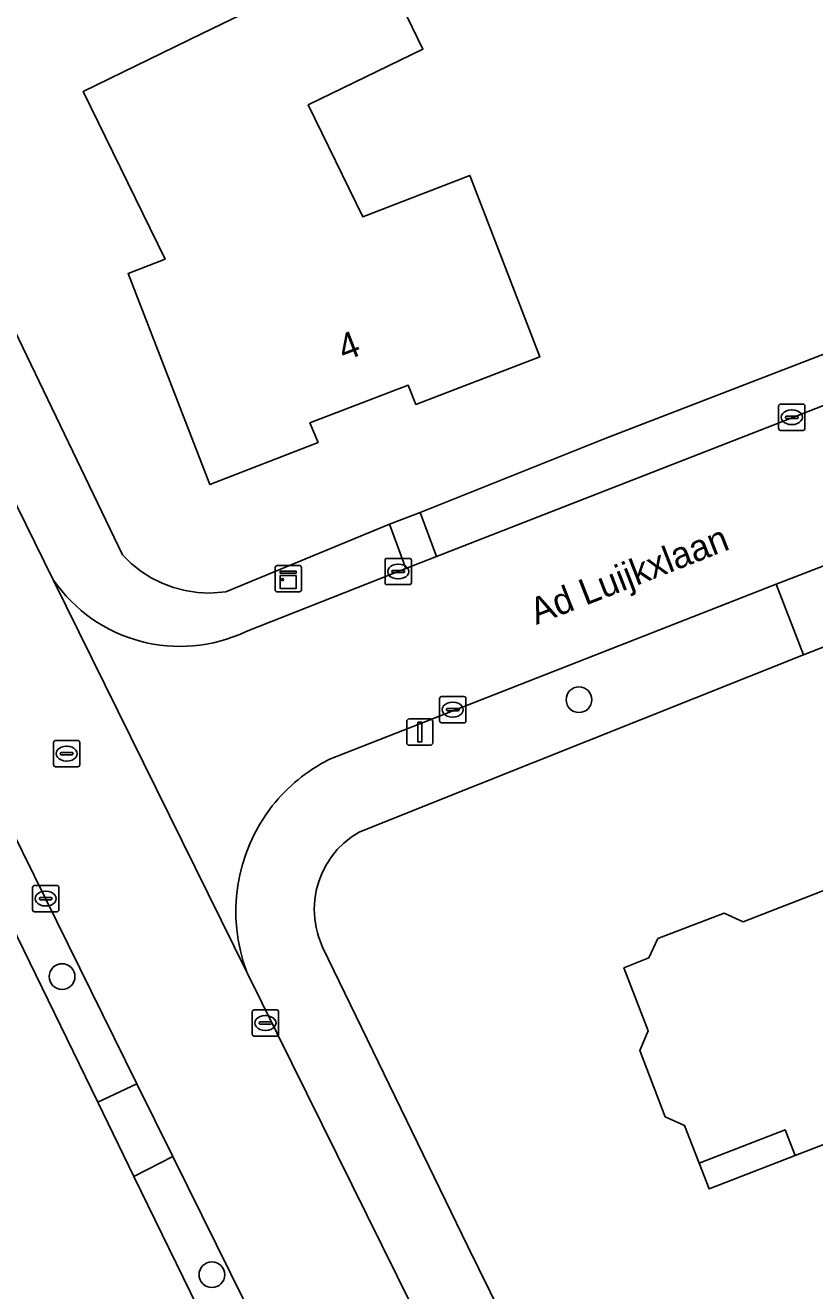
# Model space of a CAD drawing. Extents: x 157320 to 158835, y 386650 to 388491.
# Drawn here: x 158149.26 to 158179.28, y 386981.58 to 387029.67 of the extents above; entities that cross this region are included whole.
import ezdxf

# ---------------------------------------------------------------- set-up
doc = ezdxf.new("R2010")
doc.units = 0
for name, color, linetype in [('IMGEO_Boom', 7, 'Continuous'), ('IMGEO_Erf', 7, 'Continuous'), ('IMGEO_Groenvoorziening', 7, 'Continuous'), ('IMGEO_Hek', 7, 'Continuous'), ('IMGEO_Kast', 7, 'Continuous'), ('IMGEO_Kolk', 7, 'Continuous'), ('IMGEO_Lichtmast', 7, 'Continuous'), ('IMGEO_Openbare_ruimte_label', 7, 'Continuous'), ('IMGEO_Pand', 7, 'Continuous'), ('IMGEO_Pand_nummerreeks', 7, 'Continuous'), ('IMGEO_Pand_overbouw', 7, 'Continuous'), ('IMGEO_Rijbaan_lokaal_gesloten', 7, 'Continuous'), ('IMGEO_Rijbaan_lokaal_open', 7, 'Continuous'), ('IMGEO_Rioolput', 7, 'Continuous'), ('IMGEO_Voetpad_open', 7, 'Continuous')]:
    doc.layers.add(name, color=color, linetype=linetype)

msp = doc.modelspace()

# ---------------------------------------------------------------- linework, layer by layer
at = {"layer": 'IMGEO_Boom'}
for centre in [(158170.316, 387004.038), (158150.658, 386993.515), (158156.355, 386982.186)]:
    msp.add_circle(centre, 0.489, dxfattribs=at)
at = {"layer": 'IMGEO_Erf'}
for points in [[(158157.696, 386977.099), (158153.389, 386985.92), (158152.012, 386988.74), (158146.345, 387000.348), (158144.612, 387003.884), (158143.428, 387006.237), (158136.533, 387019.939), (158134.023, 387024.867), (158126.593, 387040.135), (158124.413, 387044.539), (158121.773, 387050.005), (158120.091, 387053.487), (158116.048, 387061.855)], [(158139.379, 387037.621), (158145.728, 387024.479), (158148.376, 387019.052), (158152.961, 387009.538), (158153.291, 387009.212), (158153.654, 387008.922), (158154.045, 387008.672), (158154.46, 387008.464), (158154.895, 387008.301), (158155.344, 387008.184), (158155.803, 387008.115), (158156.266, 387008.093), (158156.73, 387008.121), (158156.891, 387008.142), (158163.114, 387010.708), (158164.275, 387011.156), (158171.314, 387013.97), (158200.402, 387025.18)], [(158184.426, 387007.92), (158178.863, 387005.743), (158164.455, 387000), (158161.952, 386999.002), (158161.654, 386998.81), (158161.378, 386998.589), (158161.127, 386998.34), (158160.903, 386998.065), (158160.709, 386997.769), (158160.547, 386997.455), (158160.419, 386997.125), (158160.326, 386996.783), (158160.269, 386996.434), (158160.249, 386996.08), (158160.266, 386995.727), (158160.32, 386995.377), (158160.372, 386995.178), (158160.41, 386995.035), (158160.564, 386994.64), (158166.088, 386983.262), (158171.163, 386972.978), (158172.603, 386970.061), (158172.633, 386970.001), (158181.572, 386970.234)]]:
    msp.add_lwpolyline(points, dxfattribs=at)
for points in [[(158162.548, 387032.541), (158164.384, 387028.764), (158160.022, 387026.644), (158162.091, 387022.388), (158166.167, 387023.964), (158167.029, 387021.736), (158168.833, 387017.072), (158164.111, 387015.261), (158163.822, 387015.989), (158160.085, 387014.554), (158160.396, 387013.816), (158156.273, 387012.213), (158153.168, 387020.235), (158154.576, 387020.78), (158151.462, 387027.153), (158155.959, 387029.339), (158158.186, 387030.421)], [(158178.542, 386986.711), (158178.165, 386987.686), (158174.89, 386986.42), (158174.332, 386987.858), (158173.596, 386988.189), (158172.633, 386990.713), (158172.947, 386991.453), (158172.026, 386993.842), (158172.975, 386994.229), (158173.318, 386994.96), (158175.841, 386995.929), (158176.56, 386995.601), (158177.54, 386995.981), (158182.364, 386997.85), (158187.871, 386999.983), (158191.118, 386991.57)]]:
    msp.add_lwpolyline(points, close=True, dxfattribs=at)
at = {"layer": 'IMGEO_Groenvoorziening'}
for points in [[(158164.899, 387009.476), (158178.74, 387014.873), (158208.687, 387026.576), (158208.12, 387028.081), (158200.402, 387025.18), (158171.314, 387013.97), (158164.275, 387011.156)], [(158148.28, 387000), (158147.728, 387001.115), (158146.345, 387000.348), (158152.012, 386988.74), (158153.505, 386989.437)], [(158154.869, 386986.68), (158153.389, 386985.92), (158157.696, 386977.099), (158159.268, 386977.788)]]:
    msp.add_lwpolyline(points, close=True, dxfattribs=at)
for points in [[(158148.376, 387019.052), (158145.782, 387017.803), (158150.323, 387008.595)], [(158157.658, 387006.628), (158163.738, 387009.023), (158163.114, 387010.708), (158156.891, 387008.142), (158156.73, 387008.121), (158156.266, 387008.093), (158155.803, 387008.115), (158155.344, 387008.184), (158154.895, 387008.301), (158154.46, 387008.464), (158154.045, 387008.672), (158153.654, 387008.922), (158153.291, 387009.212), (158152.961, 387009.538), (158148.376, 387019.052)], [(158166.088, 386983.262), (158160.564, 386994.64), (158160.41, 386995.035), (158160.372, 386995.178), (158160.32, 386995.377), (158160.266, 386995.727), (158160.249, 386996.08), (158160.269, 386996.434), (158160.326, 386996.783), (158160.419, 386997.125), (158160.547, 386997.455), (158160.709, 386997.769), (158160.903, 386998.065), (158161.127, 386998.34), (158161.378, 386998.589), (158161.654, 386998.81), (158161.952, 386999.002), (158164.455, 387000), (158178.863, 387005.743), (158177.812, 387008.426), (158160.803, 387001.762)], [(158157.688, 386993.689), (158168.543, 386971.758), (158169.454, 386969.918), (158172.633, 386970.001), (158172.603, 386970.061), (158171.163, 386972.978), (158166.088, 386983.262)]]:
    msp.add_lwpolyline(points, dxfattribs=at)
for centre, radius, start, end in [((158155.148, 387011.929), 5.865, 214.6391, 295.3377), ((158163.724, 386996.011), 6.451, 116.9263, 141.7977), ((158163.743, 386995.991), 6.478, 141.7635, 200.8138)]:
    msp.add_arc(centre, radius, start, end, dxfattribs=at)
at = {"layer": 'IMGEO_Hek'}
for points in [[(158171.314, 387013.97), (158200.402, 387025.18)], [(158171.163, 386972.978), (158166.088, 386983.262)]]:
    msp.add_lwpolyline(points, dxfattribs=at)
at = {"layer": 'IMGEO_Kast'}
for p, q in [((158158.839, 387009.137), (158159.68, 387009.137)), ((158159.68, 387009.137), (158158.839, 387009.137)), ((158158.764, 387008.212), (158158.764, 387009.053)), ((158158.764, 387009.053), (158158.764, 387008.212)), ((158159.764, 387009.062), (158159.764, 387008.221)), ((158159.764, 387008.221), (158159.764, 387009.062)), ((158159.689, 387008.137), (158158.848, 387008.137)), ((158158.848, 387008.137), (158159.689, 387008.137))]:
    msp.add_line(p, q, dxfattribs=at)
for points in [[(158158.959, 387008.927), (158159.559, 387008.927), (158159.559, 387008.842), (158158.959, 387008.842), (158158.959, 387008.927)], [(158158.959, 387008.752), (158159.559, 387008.752), (158159.559, 387008.263), (158158.959, 387008.263), (158158.959, 387008.752)]]:
    msp.add_lwpolyline(points, dxfattribs=at)
msp.add_circle((158159.043, 387008.601), 0.0377, dxfattribs=at)
for centre, start, end in [((158158.842, 387009.059), 92.4484, 184.2845), ((158158.842, 387009.059), 92.4484, 184.2845), ((158159.686, 387009.059), 2.4484, 94.2845), ((158159.686, 387009.059), 2.4484, 94.2845), ((158158.842, 387008.215), 182.4484, 274.2845), ((158158.842, 387008.215), 182.4484, 274.2845), ((158159.686, 387008.215), 272.4484, 4.2845), ((158159.686, 387008.215), 272.4484, 4.2845)]:
    msp.add_arc(centre, 0.0779, start, end, dxfattribs=at)
at = {"layer": 'IMGEO_Kolk'}
for p, q in [((158177.912, 387014.346), (158177.912, 387015.198)), ((158177.987, 387015.272), (158178.839, 387015.272)), ((158178.4, 387015.052), (158178.425, 387015.052)), ((158178.913, 387015.198), (158178.913, 387014.346)), ((158178.171, 387014.766), (158178.171, 387014.778)), ((158178.609, 387014.729), (158178.211, 387014.729)), ((158178.214, 387014.815), (158178.612, 387014.815)), ((158178.423, 387014.492), (158178.398, 387014.492)), ((158178.655, 387014.778), (158178.655, 387014.766)), ((158178.839, 387014.272), (158177.987, 387014.272)), ((158162.942, 387008.484), (158162.942, 387009.336)), ((158163.017, 387009.41), (158163.869, 387009.41)), ((158163.43, 387009.19), (158163.455, 387009.19)), ((158163.943, 387009.336), (158163.943, 387008.484)), ((158163.201, 387008.904), (158163.201, 387008.916)), ((158163.639, 387008.867), (158163.241, 387008.867)), ((158163.244, 387008.953), (158163.642, 387008.953)), ((158163.685, 387008.916), (158163.685, 387008.904)), ((158163.869, 387008.41), (158163.017, 387008.41)), ((158163.453, 387008.63), (158163.428, 387008.63)), ((158165.017, 387003.233), (158165.017, 387004.085)), ((158165.092, 387004.159), (158165.944, 387004.159)), ((158165.505, 387003.939), (158165.53, 387003.939)), ((158166.018, 387004.085), (158166.018, 387003.233)), ((158165.276, 387003.653), (158165.276, 387003.665)), ((158165.714, 387003.616), (158165.316, 387003.616)), ((158165.319, 387003.702), (158165.717, 387003.702)), ((158165.528, 387003.379), (158165.503, 387003.379)), ((158165.76, 387003.665), (158165.76, 387003.653)), ((158165.944, 387003.159), (158165.092, 387003.159)), ((158149.535, 386996.053), (158149.535, 386996.905)), ((158149.61, 386996.979), (158150.462, 386996.979)), ((158150.023, 386996.759), (158150.048, 386996.759)), ((158150.536, 386996.905), (158150.536, 386996.053)), ((158149.794, 386996.473), (158149.794, 386996.485)), ((158150.232, 386996.436), (158149.834, 386996.436)), ((158149.837, 386996.522), (158150.235, 386996.522)), ((158150.046, 386996.199), (158150.021, 386996.199)), ((158150.278, 386996.485), (158150.278, 386996.473)), ((158150.462, 386995.979), (158149.61, 386995.979)), ((158157.893, 386991.325), (158157.893, 386992.177)), ((158157.968, 386992.251), (158158.82, 386992.251)), ((158158.381, 386992.031), (158158.406, 386992.031)), ((158158.894, 386992.177), (158158.894, 386991.325)), ((158158.152, 386991.745), (158158.152, 386991.757)), ((158158.59, 386991.708), (158158.192, 386991.708)), ((158158.195, 386991.794), (158158.593, 386991.794)), ((158158.404, 386991.471), (158158.379, 386991.471)), ((158158.636, 386991.757), (158158.636, 386991.745)), ((158158.82, 386991.251), (158157.968, 386991.251))]:
    msp.add_line(p, q, dxfattribs=at)
for points in [[(158177.912, 387014.346), (158177.912, 387015.198)], [(158177.987, 387015.272), (158178.839, 387015.272)], [(158178.913, 387015.198), (158178.913, 387014.346)], [(158178.839, 387014.272), (158177.987, 387014.272)], [(158162.942, 387008.484), (158162.942, 387009.336)], [(158163.017, 387009.41), (158163.869, 387009.41)], [(158163.943, 387009.336), (158163.943, 387008.484)], [(158163.869, 387008.41), (158163.017, 387008.41)], [(158165.017, 387003.233), (158165.017, 387004.085)], [(158165.092, 387004.159), (158165.944, 387004.159)], [(158166.018, 387004.085), (158166.018, 387003.233)], [(158165.944, 387003.159), (158165.092, 387003.159)], [(158149.535, 386996.053), (158149.535, 386996.905)], [(158149.61, 386996.979), (158150.462, 386996.979)], [(158150.536, 386996.905), (158150.536, 386996.053)], [(158150.462, 386995.979), (158149.61, 386995.979)], [(158157.893, 386991.325), (158157.893, 386992.177)], [(158157.968, 386992.251), (158158.82, 386992.251)], [(158158.894, 386992.177), (158158.894, 386991.325)], [(158158.82, 386991.251), (158157.968, 386991.251)]]:
    msp.add_lwpolyline(points, dxfattribs=at)
for centre, radius, start, end in [((158177.989, 387015.196), 0.0765, 91.552, 178.448), ((158177.989, 387015.196), 0.0765, 91.552, 178.448), ((158178.837, 387015.196), 0.0765, 1.552, 88.448), ((158178.837, 387015.196), 0.0765, 1.552, 88.448), ((158178.211, 387014.775), 0.0403, 85.8775, 175.7526), ((158178.208, 387014.765), 0.0366, 178.938, 274.7102), ((158178.612, 387014.772), 0.043, 264.8664, 352.4533), ((158178.616, 387014.777), 0.0386, 1.7309, 96.639), ((158177.989, 387014.348), 0.0765, 181.552, 268.448), ((158177.989, 387014.348), 0.0765, 181.552, 268.448), ((158178.837, 387014.348), 0.0765, 271.552, 358.448), ((158178.837, 387014.348), 0.0765, 271.552, 358.448), ((158163.019, 387009.334), 0.0765, 91.552, 178.448), ((158163.019, 387009.334), 0.0765, 91.552, 178.448), ((158163.867, 387009.334), 0.0765, 1.552, 88.448), ((158163.867, 387009.334), 0.0765, 1.552, 88.448), ((158163.241, 387008.913), 0.0403, 85.8775, 175.7526), ((158163.238, 387008.903), 0.0366, 178.938, 274.7102), ((158163.642, 387008.91), 0.043, 264.8664, 352.4533), ((158163.646, 387008.915), 0.0386, 1.7309, 96.639), ((158163.019, 387008.486), 0.0765, 181.552, 268.448), ((158163.019, 387008.486), 0.0765, 181.552, 268.448), ((158163.867, 387008.486), 0.0765, 271.552, 358.448), ((158163.867, 387008.486), 0.0765, 271.552, 358.448), ((158165.094, 387004.083), 0.0765, 91.552, 178.448), ((158165.094, 387004.083), 0.0765, 91.552, 178.448), ((158165.942, 387004.083), 0.0765, 1.552, 88.448), ((158165.942, 387004.083), 0.0765, 1.552, 88.448), ((158165.316, 387003.662), 0.0403, 85.8775, 175.7526), ((158165.313, 387003.652), 0.0366, 178.938, 274.7102), ((158165.717, 387003.659), 0.043, 264.8664, 352.4533), ((158165.721, 387003.664), 0.0386, 1.7309, 96.639), ((158165.094, 387003.235), 0.0765, 181.552, 268.448), ((158165.094, 387003.235), 0.0765, 181.552, 268.448), ((158165.942, 387003.235), 0.0765, 271.552, 358.448), ((158165.942, 387003.235), 0.0765, 271.552, 358.448), ((158149.612, 386996.903), 0.0765, 91.552, 178.448), ((158149.612, 386996.903), 0.0765, 91.552, 178.448), ((158150.46, 386996.903), 0.0765, 1.552, 88.448), ((158150.46, 386996.903), 0.0765, 1.552, 88.448), ((158149.834, 386996.482), 0.0403, 85.8775, 175.7526), ((158149.831, 386996.472), 0.0366, 178.938, 274.7102), ((158150.235, 386996.479), 0.043, 264.8664, 352.4533), ((158150.239, 386996.484), 0.0386, 1.7309, 96.639), ((158149.612, 386996.055), 0.0765, 181.552, 268.448), ((158149.612, 386996.055), 0.0765, 181.552, 268.448), ((158150.46, 386996.055), 0.0765, 271.552, 358.448), ((158150.46, 386996.055), 0.0765, 271.552, 358.448), ((158157.97, 386992.175), 0.0765, 91.552, 178.448), ((158157.97, 386992.175), 0.0765, 91.552, 178.448), ((158158.818, 386992.175), 0.0765, 1.552, 88.448), ((158158.818, 386992.175), 0.0765, 1.552, 88.448), ((158158.192, 386991.754), 0.0403, 85.8775, 175.7526), ((158158.189, 386991.744), 0.0366, 178.938, 274.7102), ((158158.593, 386991.751), 0.043, 264.8664, 352.4533), ((158158.597, 386991.756), 0.0386, 1.7309, 96.639), ((158157.97, 386991.327), 0.0765, 181.552, 268.448), ((158157.97, 386991.327), 0.0765, 181.552, 268.448), ((158158.818, 386991.327), 0.0765, 271.552, 358.448), ((158158.818, 386991.327), 0.0765, 271.552, 358.448)]:
    msp.add_arc(centre, radius, start, end, dxfattribs=at)
for centre, major_axis, ratio, start_param, end_param in [((158178.399, 387014.772), (-0.387, 0.002), 0.722429, 4.712389, 7.853982), ((158178.424, 387014.772), (-0.39, 0.002), 0.717154, 1.570796, 4.712389), ((158163.429, 387008.91), (-0.387, 0.002), 0.722429, 4.712389, 7.853982), ((158163.454, 387008.91), (-0.39, 0.002), 0.717154, 1.570796, 4.712389), ((158165.504, 387003.659), (-0.387, 0.002), 0.722429, 4.712389, 7.853982), ((158165.529, 387003.659), (-0.39, 0.002), 0.717154, 1.570796, 4.712389), ((158150.022, 386996.479), (-0.387, 0.002), 0.722429, 4.712389, 7.853982), ((158150.047, 386996.479), (-0.39, 0.002), 0.717154, 1.570796, 4.712389), ((158158.38, 386991.751), (-0.387, 0.002), 0.722429, 4.712389, 7.853982), ((158158.405, 386991.751), (-0.39, 0.002), 0.717154, 1.570796, 4.712389)]:
    msp.add_ellipse(centre, major_axis=major_axis, ratio=ratio, start_param=start_param, end_param=end_param, dxfattribs=at)
at = {"layer": 'IMGEO_Lichtmast'}
for p, q in [((158163.766, 387002.406), (158163.766, 387003.206)), ((158163.766, 387003.206), (158163.766, 387002.406)), ((158163.866, 387003.306), (158164.656, 387003.306)), ((158164.656, 387003.306), (158163.866, 387003.306)), ((158164.756, 387003.206), (158164.756, 387002.406)), ((158164.756, 387002.406), (158164.756, 387003.206)), ((158164.656, 387002.306), (158163.866, 387002.306)), ((158163.866, 387002.306), (158164.656, 387002.306))]:
    msp.add_line(p, q, dxfattribs=at)
msp.add_lwpolyline([(158164.186, 387003.181), (158164.336, 387003.181), (158164.336, 387002.431), (158164.186, 387002.431), (158164.186, 387003.181)], dxfattribs=at)
for centre, start, end in [((158163.866, 387003.206), 90, 180), ((158163.866, 387003.206), 90, 180), ((158164.656, 387003.206), 0, 90), ((158164.656, 387003.206), 360, 90), ((158163.866, 387002.406), 180, 270), ((158163.866, 387002.406), 180, 270), ((158164.656, 387002.406), 270, 0), ((158164.656, 387002.406), 270, 0)]:
    msp.add_arc(centre, 0.1, start, end, dxfattribs=at)
at = {"layer": 'IMGEO_Pand'}
for points in [[(158167.029, 387021.736), (158166.167, 387023.964), (158162.091, 387022.388), (158160.022, 387026.644), (158164.384, 387028.764), (158162.548, 387032.541), (158158.186, 387030.421), (158155.959, 387029.339), (158151.462, 387027.153), (158154.576, 387020.78), (158153.168, 387020.235), (158156.273, 387012.213), (158160.396, 387013.816), (158160.085, 387014.554), (158163.822, 387015.989), (158164.111, 387015.261), (158168.833, 387017.072)], [(158187.871, 386999.983), (158182.364, 386997.85), (158177.54, 386995.981), (158176.56, 386995.601), (158175.841, 386995.929), (158173.318, 386994.96), (158172.975, 386994.229), (158172.026, 386993.842), (158172.947, 386991.453), (158172.633, 386990.713), (158173.596, 386988.189), (158174.332, 386987.858), (158174.89, 386986.42), (158178.165, 386987.686), (158178.542, 386986.711), (158191.118, 386991.57)]]:
    msp.add_lwpolyline(points, close=True, dxfattribs=at)
at = {"layer": 'IMGEO_Pand_overbouw'}
msp.add_lwpolyline([(158178.542, 386986.711), (158178.165, 386987.686), (158174.89, 386986.42), (158175.267, 386985.446)], close=True, dxfattribs=at)
at = {"layer": 'IMGEO_Rijbaan_lokaal_gesloten'}
for points in [[(158117.764, 387061.714), (158121.061, 387055.057), (158123.554, 387050.025), (158125.905, 387045.279), (158128.087, 387040.873), (158135.604, 387025.647), (158138.057, 387020.691), (158144.844, 387006.936), (158145.986, 387004.623), (158147.728, 387001.115), (158148.28, 387000), (158153.505, 386989.437), (158154.869, 386986.68), (158159.268, 386977.788), (158160.708, 386974.875), (158162.973, 386970.296), (158164.386, 386967.433), (158169.454, 386969.918), (158168.543, 386971.758), (158157.688, 386993.689), (158150.323, 387008.595), (158145.782, 387017.803), (158143.102, 387023.21), (158136.706, 387036.184)], [(158210.032, 387027.043), (158208.687, 387026.576), (158178.74, 387014.873), (158164.899, 387009.476), (158163.738, 387009.023), (158157.658, 387006.628)], [(158160.803, 387001.762), (158177.812, 387008.426), (158183.373, 387010.572), (158195.353, 387015.242)], [(158150.323, 387008.595), (158157.688, 386993.689)]]:
    msp.add_lwpolyline(points, dxfattribs=at)
for centre, radius, start, end in [((158155.148, 387011.929), 5.865, 214.6391, 295.3377), ((158163.724, 386996.011), 6.451, 116.9263, 141.7977), ((158163.743, 386995.991), 6.478, 141.7635, 200.8138)]:
    msp.add_arc(centre, radius, start, end, dxfattribs=at)
at = {"layer": 'IMGEO_Rijbaan_lokaal_open'}
msp.add_lwpolyline([(158153.505, 386989.437), (158152.012, 386988.74), (158153.389, 386985.92), (158154.869, 386986.68)], close=True, dxfattribs=at)
at = {"layer": 'IMGEO_Rioolput'}
for p, q in [((158150.332, 387001.562), (158150.332, 387002.414)), ((158150.407, 387002.488), (158151.259, 387002.488)), ((158151.333, 387002.414), (158151.333, 387001.562)), ((158150.591, 387001.982), (158150.591, 387001.994)), ((158151.029, 387001.945), (158150.631, 387001.945)), ((158150.634, 387002.031), (158151.032, 387002.031)), ((158150.82, 387002.268), (158150.845, 387002.268)), ((158151.075, 387001.994), (158151.075, 387001.982)), ((158151.259, 387001.488), (158150.407, 387001.488)), ((158150.843, 387001.708), (158150.818, 387001.708))]:
    msp.add_line(p, q, dxfattribs=at)
for points in [[(158150.332, 387001.562), (158150.332, 387002.414)], [(158150.407, 387002.488), (158151.259, 387002.488)], [(158151.333, 387002.414), (158151.333, 387001.562)], [(158151.259, 387001.488), (158150.407, 387001.488)]]:
    msp.add_lwpolyline(points, dxfattribs=at)
for centre, radius, start, end in [((158150.409, 387002.412), 0.0765, 91.552, 178.448), ((158150.409, 387002.412), 0.0765, 91.552, 178.448), ((158151.257, 387002.412), 0.0765, 1.552, 88.448), ((158151.257, 387002.412), 0.0765, 1.552, 88.448), ((158150.631, 387001.991), 0.0403, 85.8775, 175.7526), ((158150.628, 387001.981), 0.0366, 178.938, 274.7102), ((158151.032, 387001.988), 0.043, 264.8664, 352.4533), ((158151.036, 387001.993), 0.0386, 1.7309, 96.639), ((158150.409, 387001.564), 0.0765, 181.552, 268.448), ((158150.409, 387001.564), 0.0765, 181.552, 268.448), ((158151.257, 387001.564), 0.0765, 271.552, 358.448), ((158151.257, 387001.564), 0.0765, 271.552, 358.448)]:
    msp.add_arc(centre, radius, start, end, dxfattribs=at)
for centre, major_axis, ratio, start_param, end_param in [((158150.819, 387001.988), (-0.387, 0.002), 0.722429, 4.712389, 7.853982), ((158150.844, 387001.988), (-0.39, 0.002), 0.717154, 1.570796, 4.712389)]:
    msp.add_ellipse(centre, major_axis=major_axis, ratio=ratio, start_param=start_param, end_param=end_param, dxfattribs=at)
at = {"layer": 'IMGEO_Voetpad_open'}
for points in [[(158164.275, 387011.156), (158163.114, 387010.708), (158163.738, 387009.023), (158164.899, 387009.476)], [(158183.373, 387010.572), (158177.812, 387008.426), (158178.863, 387005.743), (158184.426, 387007.92)]]:
    msp.add_lwpolyline(points, close=True, dxfattribs=at)

# ---------------------------------------------------------------- texts
at = {"layer": 'IMGEO_Openbare_ruimte_label'}
msp.add_text('Ad Luijkxlaan', height=1, rotation=21.3335, dxfattribs=at).set_placement((158168.694, 387006.878))
at = {"layer": 'IMGEO_Pand_nummerreeks'}
msp.add_text('4', height=1, rotation=21.1496, dxfattribs=at).set_placement((158161.387, 387016.893))

doc.saveas('drawing.dxf')
